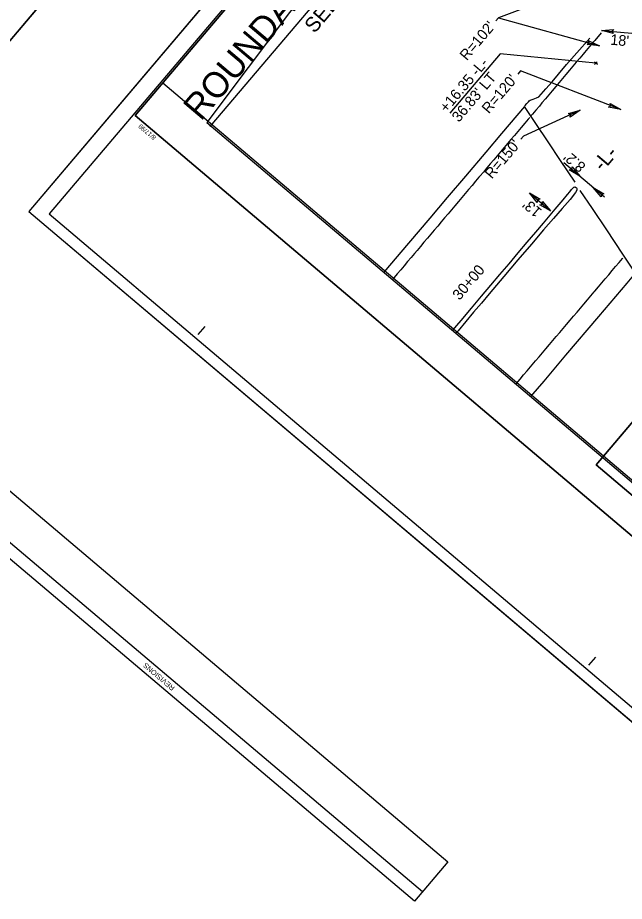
# Model space of a CAD drawing. Extents: x 1761753 to 1762923, y 422186 to 423380.
# Drawn here: x 1762148.4 to 1762432.8, y 422185.5 to 422600.2 of the extents above; entities that cross this region are included whole.
import ezdxf

# ---------------------------------------------------------------- set-up
doc = ezdxf.new("R2010")
doc.units = 0
for name, color, linetype in [('Default', 7, 'Continuous'), ('Exist Roads Curbs', 7, 'Continuous'), ('Prop Conc 2ft 6in Curb and Gutter', 7, 'Continuous'), ('Prop Conc 5in Monolithic Keyed In Island', 7, 'Continuous'), ('Prop Dimension Text', 7, 'Continuous'), ('Prop Grid Mask', 7, 'Continuous'), ('Prop Horizontal Alignment Station Label', 7, 'Continuous'), ('Prop RDY Traffic Signal CELL', 7, 'Continuous'), ('Prop Shade Heavy', 7, 'Continuous'), ('Sheet Cutting Line CELL', 7, 'Continuous'), ('Sheet Data Field CELL', 7, 'Continuous'), ('Sheet Layout Plan Border', 7, 'Continuous'), ('Sheet North Arrow CELL', 7, 'Continuous'), ('Sheet Plan CELL', 7, 'Continuous'), ('Sheet Plan Layout CELL', 7, 'Continuous'), ('Sheet Plot Border Outside CELL', 7, 'Continuous'), ('Sheet Symbology CELL', 7, 'Continuous')]:
    doc.layers.add(name, color=color, linetype=linetype)

# ---------------------------------------------------------------- blocks, each defined once
blk = doc.blocks.new('Terminator')
at = {"layer": 'Sheet Data Field CELL'}
blk.add_lwpolyline([(-9, 1.55), (0, 0), (-9.05, -1.6), (-7.9, 0)], close=True, dxfattribs=at)

msp = doc.modelspace()

# ---------------------------------------------------------------- linework, layer by layer
at = {"layer": 'Default'}
for p, q in [((1762419.31, 422579.02), (1762418.73, 422579.51)), ((1762420.15, 422578.32), (1762419.31, 422579.02))]:
    msp.add_line(p, q, dxfattribs=at)
at = {"layer": 'Exist Roads Curbs'}
msp.add_lwpolyline([(1762352.26, 422453.45), (1762356.23, 422458.13), (1762361.16, 422463.96), (1762365.82, 422469.46), (1762370.2, 422474.65), (1762374.46, 422479.69), (1762378.72, 422484.74), (1762383, 422489.8), (1762387.28, 422494.87), (1762391.32, 422499.64), (1762394.85, 422503.81), (1762400.43, 422510.35), (1762404.16, 422514.72), (1762406.2, 422517.18), (1762407.28, 422518.52), (1762408.09, 422519.56), (1762408.69, 422520.28), (1762408.94, 422520.51), (1762409.14, 422520.66), (1762409.33, 422520.75), (1762409.52, 422520.77), (1762409.72, 422520.75), (1762409.92, 422520.67), (1762410.11, 422520.53), (1762410.29, 422520.34), (1762410.44, 422520.08), (1762410.58, 422519.77), (1762410.47, 422519.21), (1762409.9, 422518.22), (1762407.36, 422514.97), (1762403.69, 422510.67), (1762399.64, 422506.01), (1762394.91, 422500.59), (1762389.21, 422493.98), (1762382.89, 422486.58), (1762379.62, 422482.72), (1762376.29, 422478.76), (1762372.87, 422474.7), (1762369.38, 422470.55), (1762365.81, 422466.31), (1762362.15, 422461.97), (1762358.48, 422457.62), (1762354.84, 422453.31), (1762353.83, 422452.12)], dxfattribs=at)
at = {"layer": 'Prop Conc 2ft 6in Curb and Gutter'}
msp.add_lwpolyline([(1762485.08, 422235.35), (1762915.83, 422743.82), (1762593.84, 423016.59), (1762163.09, 422508.12)], close=True, dxfattribs=at)
at = {"layer": 'Prop Conc 5in Monolithic Keyed In Island'}
msp.add_line((1762238.69, 422549.2), (1762392.09, 422730.28), dxfattribs=at)
msp.add_lwpolyline([(1762419.59, 422390.33), (1762528.88, 422519.33), (1762632.05, 422431.93), (1762522.76, 422302.93)], close=True, dxfattribs=at)
at = {"layer": 'Prop Dimension Text'}
for p, q in [((1762108.95, 422547.17), (1762544.23, 423060.98)), ((1762588.9, 423023.14), (1762153.62, 422509.33)), ((1762153.62, 422509.33), (1762487.82, 422226.21))]:
    msp.add_line(p, q, dxfattribs=at)
at = {"layer": 'Prop Grid Mask'}
for p, q in [((1762203.53, 422554.33), (1762203.53, 422554.33)), ((1762233.05, 422451.47), (1762236.28, 422455.29)), ((1762416.18, 422296.35), (1762419.41, 422300.16))]:
    msp.add_line(p, q, dxfattribs=at)
for points in [[(1762591.38, 423012.14), (1762203.53, 422554.33), (1762524, 422282.84), (1762911.83, 422740.65)], [(1762524, 422282.84), (1762203.54, 422554.31), (1762539.64, 422951.08), (1762585.45, 422912.29), (1762637.17, 422973.33), (1762911.83, 422740.65)]]:
    msp.add_lwpolyline(points, close=True, dxfattribs=at)
at = {"layer": 'Prop Horizontal Alignment Station Label'}
for points in [[(1762523.28, 422308.57), (1762722.11, 422543.28), (1762725.69, 422557.29), (1762715.43, 422577.81), (1762620.66, 422667), (1762762.51, 422846.79), (1762681.74, 422915.22), (1762532.27, 422738.78), (1762453.01, 422805.92), (1762420.01, 422792.47), (1762392.6, 422758.24), (1762237.08, 422551.03)], [(1762523.28, 422308.57), (1762722.11, 422543.28), (1762725.69, 422557.29), (1762715.43, 422577.81), (1762620.66, 422667), (1762762.51, 422846.79), (1762681.74, 422915.22), (1762532.27, 422738.78), (1762453.01, 422805.92), (1762420.01, 422792.47), (1762392.6, 422758.24), (1762237.08, 422551.03)], [(1762522.76, 422302.93), (1762632.05, 422431.93), (1762604.08, 422455.62), (1762574.02, 422455.04), (1762547.43, 422462.1), (1762516.58, 422504.82), (1762419.59, 422390.33)]]:
    msp.add_lwpolyline(points, close=True, dxfattribs=at)
at = {"layer": 'Prop RDY Traffic Signal CELL'}
msp.add_lwpolyline([(1762203.54, 422554.31), (1762524, 422282.84), (1762911.83, 422740.65), (1762655.91, 422957.45), (1762594.05, 422884.43), (1762529.51, 422939.11)], close=True, dxfattribs=at)
at = {"layer": 'Prop Shade Heavy'}
msp.add_line((1762338.12, 422190), (1762096.82, 422394.42), dxfattribs=at)
msp.add_lwpolyline([(1762334.37, 422185.55), (1762093.06, 422389.98), (1762108.71, 422408.46), (1762350.02, 422204.03)], close=True, dxfattribs=at)
at = {"layer": 'Sheet Cutting Line CELL'}
msp.add_lwpolyline([(1762386.11, 422558.77), (1762387.1, 422559.92), (1762387.89, 422560.8), (1762388.24, 422561.14), (1762388.63, 422561.43), (1762389.05, 422561.66), (1762390.05, 422562.01), (1762391.62, 422562.62), (1762392.66, 422563.05), (1762396.05, 422566.84), (1762398.93, 422570.15), (1762401.94, 422573.69), (1762405.72, 422578.17), (1762410.51, 422583.76), (1762416.54, 422590.65)], dxfattribs=at)
at = {"layer": 'Sheet Data Field CELL'}
msp.add_lwpolyline([(1762421.93, 422516.12), (1762418.24, 422520.53), (1762423.24, 422517.61), (1762422.03, 422517.31)], close=True, dxfattribs=at)
at = {"layer": 'Sheet Layout Plan Border'}
for points in [[(1762409.68, 422522.97), (1762402.89, 422533.19), (1762397.04, 422541.98), (1762391.29, 422550.6), (1762385.95, 422558.59), (1762375.22, 422545.89), (1762367.87, 422537.18), (1762358.28, 422525.87), (1762349.73, 422515.78), (1762341.56, 422506.12), (1762331.63, 422494.43), (1762320.01, 422480.77)], [(1762388.95, 422422.37), (1762395.13, 422429.63), (1762405.36, 422441.85), (1762420.87, 422460.03), (1762434.04, 422475.59), (1762438.01, 422480.28), (1762432.16, 422489.19), (1762424.54, 422500.66), (1762417.86, 422510.63), (1762412.15, 422519.18)]]:
    msp.add_lwpolyline(points, dxfattribs=at)
at = {"layer": 'Sheet North Arrow CELL'}
for points in [[(1762108.95, 422547.17), (1762544.23, 423060.98), (1762210.03, 423344.1), (1761774.75, 422830.29)], [(1762487.82, 422226.21), (1762923.1, 422740.02), (1762588.9, 423023.14), (1762153.62, 422509.33)]]:
    msp.add_lwpolyline(points, close=True, dxfattribs=at)
at = {"layer": 'Sheet Plan CELL'}
for p, q in [((1762373.76, 422600.17), (1762421.11, 422587.08)), ((1762422.01, 422594.23), (1762439.93, 422592.62)), ((1762418.73, 422579.51), (1762420.15, 422578.32)), ((1762419.98, 422579.55), (1762418.83, 422578.2)), ((1762404.36, 422532.28), (1762423.41, 422516.14)), ((1762388.27, 422517.95), (1762398.19, 422509.55))]:
    msp.add_line(p, q, dxfattribs=at)
for points in [[(1762421.36, 422618.07), (1762373.76, 422600.17), (1762372.52, 422598.71)], [(1762419.44, 422578.92), (1762374.56, 422583.26), (1762350.93, 422555.36)], [(1762431.11, 422557.06), (1762384.11, 422575.23), (1762382.87, 422573.77)], [(1762412.1, 422556.78), (1762385.51, 422544.65), (1762384.27, 422543.18)]]:
    msp.add_lwpolyline(points, dxfattribs=at)
at = {"layer": 'Sheet Plan Layout CELL'}
for points in [[(1762421.9, 422593.14), (1762418.88, 422589.58), (1762417.27, 422587.67), (1762415.65, 422585.76), (1762414.04, 422583.86), (1762413.46, 422583.17), (1762411.85, 422581.26), (1762410.24, 422579.35), (1762408.64, 422577.43), (1762407.03, 422575.52), (1762405.42, 422573.6), (1762403.82, 422571.69), (1762402.21, 422569.77), (1762400.6, 422567.86), (1762399, 422565.94), (1762397.39, 422564.03), (1762395.79, 422562.11), (1762394.18, 422560.2), (1762392.97, 422558.76), (1762391.36, 422556.86), (1762389.75, 422554.95), (1762389.15, 422554.24)], [(1762388.42, 422553.38), (1762387.73, 422552.56), (1762386.11, 422550.66), (1762384.49, 422548.75), (1762382.88, 422546.85), (1762381.26, 422544.94), (1762379.64, 422543.04), (1762378.03, 422541.13), (1762376.41, 422539.23), (1762374.79, 422537.32), (1762373.18, 422535.41), (1762371.56, 422533.51), (1762369.94, 422531.6), (1762368.32, 422529.7), (1762366.71, 422527.79), (1762365.09, 422525.89), (1762364.64, 422525.36), (1762363.03, 422523.45), (1762361.42, 422521.54), (1762359.8, 422519.63), (1762358.19, 422517.72), (1762356.58, 422515.81), (1762354.97, 422513.9), (1762353.36, 422511.99), (1762351.75, 422510.08), (1762350.13, 422508.17), (1762348.52, 422506.26), (1762346.91, 422504.35), (1762345.3, 422502.44), (1762343.69, 422500.53), (1762342.08, 422498.62), (1762340.46, 422496.71), (1762338.85, 422494.8), (1762337.24, 422492.89), (1762335.63, 422490.98), (1762334.43, 422489.56), (1762332.82, 422487.66), (1762331.21, 422485.75), (1762329.59, 422483.84), (1762327.98, 422481.93), (1762326.37, 422480.02), (1762324.08, 422477.32)], [(1762381.97, 422428.28), (1762383.97, 422430.64), (1762385.58, 422432.55), (1762387.2, 422434.45), (1762388.82, 422436.36), (1762390.43, 422438.26), (1762391.2, 422439.17), (1762392.82, 422441.07), (1762394.43, 422442.98), (1762396.05, 422444.88), (1762397.67, 422446.79), (1762399.28, 422448.69), (1762400.9, 422450.6), (1762402.52, 422452.5), (1762404.14, 422454.41), (1762405.75, 422456.31), (1762407.37, 422458.22), (1762408.99, 422460.12), (1762410.61, 422462.03), (1762412.22, 422463.93), (1762413.84, 422465.84), (1762415.46, 422467.74), (1762417.07, 422469.65), (1762418.69, 422471.55), (1762419.03, 422471.95), (1762420.64, 422473.86), (1762422.25, 422475.77), (1762423.86, 422477.68), (1762425.47, 422479.59), (1762427.08, 422481.5), (1762428.69, 422483.42), (1762430.3, 422485.33), (1762431.91, 422487.24), (1762432.1, 422487.46)]]:
    msp.add_lwpolyline(points, dxfattribs=at)
at = {"layer": 'Sheet Symbology CELL'}
msp.add_lwpolyline([(1762536.93, 422298.1), (1762898.91, 422725.39), (1762642.99, 422942.19), (1762594.05, 422884.43), (1762529.51, 422939.11), (1762216.46, 422569.59)], close=True, dxfattribs=at)

# ---------------------------------------------------------------- block references
at = {"layer": 'Default'}
for p, xscale, yscale, rotation in [((1762422.01, 422594.23), 0.6300000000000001, 0.6299999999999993, 174.84658037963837), ((1762421.11, 422587.08), 0.63, 0.6299999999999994, -15.448940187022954), ((1762412.1, 422556.78), 0.6300000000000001, 0.6299999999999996, 24.535854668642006), ((1762431.11, 422557.06), 0.6300000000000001, 0.6299999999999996, -21.135274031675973), ((1762411.98, 422525.83), 0.63, 0.6299999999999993, -40.269896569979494), ((1762388.27, 422517.95), 0.6300000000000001, 0.6299999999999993, 139.73010343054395), ((1762398.19, 422509.55), 0.63, 0.6299999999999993, -40.269896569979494)]:
    msp.add_blockref('Terminator', p, dxfattribs=dict(at, xscale=xscale, yscale=yscale, rotation=rotation))

# ---------------------------------------------------------------- texts
at = {"layer": 'Prop Dimension Text'}
for s, height, rotation, p in [('ROUNDABOUT DETAIL (-RAB2-)', 12, 49.7301, (1762234.28, 422551.33)), ('SEE SHEET 5 FOR PLAN', 7, 49.7301, (1762287.54, 422592.54)), ("R=102'", 5, 49.7301, (1762358.93, 422579.77)), ("18'", 5, 354.8466, (1762426.07, 422587.55)), ('+16.35 -L-', 5, 49.7301, (1762349.47, 422555.33)), ("36.83' LT", 5, 49.7301, (1762355.25, 422550.83)), ("R=120'", 5, 49.7301, (1762369.28, 422554.83)), ("R=150'", 5, 49.7301, (1762370.68, 422524.24)), ("8.2'", 5, 139.7301, (1762415.09, 422530.96)), ("13'", 5, 139.7301, (1762394.47, 422509.83))]:
    msp.add_text(s, height=height, rotation=rotation, dxfattribs=at).set_placement(p)
at = {"layer": 'Prop Grid Mask'}
msp.add_text('8/17/99', height=2.1, rotation=139.7301, dxfattribs=at).set_placement((1762213.45, 422544.23))
at = {"layer": 'Prop Shade Heavy'}
msp.add_text('REVISIONS', height=2.4, rotation=139.7301, dxfattribs=at).set_placement((1762222.28, 422286.02))
at = {"layer": 'Sheet Plot Border Outside CELL'}
for s, height, p in [('-L-', 7, (1762422.66, 422527.72)), ('30+00', 5, (1762355.55, 422467.31))]:
    msp.add_text(s, height=height, rotation=49.7301, dxfattribs=at).set_placement(p)

doc.saveas('drawing.dxf')
